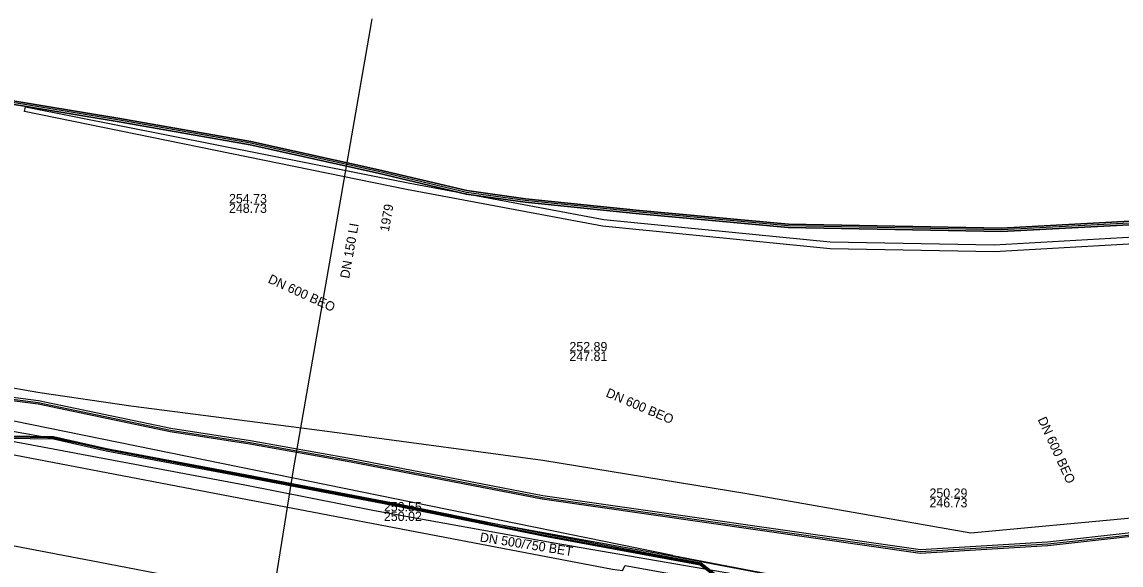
# Model space of a CAD drawing. Extents: x -599951 to -598963, y -1164095 to -1162939.
# Drawn here: x -599743.7 to -599648.8, y -1163069.7 to -1163022.9 of the extents above; entities that cross this region are included whole.
import ezdxf

# ---------------------------------------------------------------- set-up
doc = ezdxf.new("R2010")
doc.units = 0
for name, color, linetype in [('Level 3', 7, 'Continuous'), ('Vrstva 12', 7, 'Continuous'), ('Vrstva 13', 7, 'Continuous'), ('Vrstva 15', 7, 'Continuous'), ('Vrstva 20', 7, 'Continuous'), ('Vrstva 42', 7, 'Continuous'), ('Vrstva 44', 7, 'Continuous'), ('Vrstva 50', 7, 'Continuous'), ('Vrstva 55', 7, 'Continuous'), ('Vrstva 58', 7, 'Continuous')]:
    doc.layers.add(name, color=color, linetype=linetype)

msp = doc.modelspace()

# ---------------------------------------------------------------- linework, layer by layer
at = {"layer": 'Level 3'}
msp.add_lwpolyline([(-599673.93, -1163041.83), (-599659.8, -1163042.11), (-599643.7, -1163041.17), (-599629.45, -1163039.68), (-599616.06, -1163036.87), (-599614.07, -1163036.32), (-599613.87, -1163036.89), (-599615.9, -1163037.45), (-599629.35, -1163040.27), (-599643.66, -1163041.77), (-599659.78, -1163042.71), (-599673.95, -1163042.43), (-599693.58, -1163040.5), (-599710.47, -1163037.32), (-599743.44, -1163030.59), (-599743.36, -1163030.18), (-599710.35, -1163036.74), (-599693.46, -1163039.92)], close=True, dxfattribs=at)
at = {"layer": 'Vrstva 12'}
msp.add_line((-599687.5, -1163068.9), (-599771.04, -1163051.87), dxfattribs=at)
msp.add_lwpolyline([(-599687.5, -1163068.9), (-599664.38, -1163073.35), (-599656.95, -1163072.63), (-599653.54, -1163073.9), (-599642.67, -1163071.94), (-599630.66, -1163068.12), (-599627.43, -1163066.85)], dxfattribs=at)
at = {"layer": 'Vrstva 13'}
msp.add_lwpolyline([(-599713.474, -1163022.583), (-599713.543, -1163022.941), (-599715.989, -1163037.162), (-599720.271, -1163061.507), (-599722.794, -1163077.28), (-599723.393, -1163080.467), (-599723.56, -1163081.1)], dxfattribs=at)
at = {"layer": 'Vrstva 20'}
for points in [[(-599749, -1163058.61), (-599740.93, -1163058.73)], [(-599740.93, -1163058.73), (-599736.37, -1163059.77), (-599725.02, -1163061.91), (-599711.66, -1163064.47), (-599698.39, -1163067.17), (-599685.12, -1163069.63), (-599681.39, -1163072.5), (-599673.97, -1163073.86), (-599663.79, -1163075.59), (-599663.05, -1163075.2), (-599661.91, -1163074.71), (-599660.66, -1163074.4), (-599659.28, -1163074.73), (-599658.24, -1163075.53), (-599628.33, -1163084.93)]]:
    msp.add_lwpolyline(points, dxfattribs=at)
at = {"layer": 'Vrstva 42'}
for p, q in [((-599754.889, -1163052.719), (-599742.1, -1163054.827)), ((-599754.889, -1163052.719), (-599742.1, -1163054.827)), ((-599742.1, -1163054.827), (-599734.251, -1163055.996)), ((-599742.1, -1163054.827), (-599734.251, -1163055.996)), ((-599734.251, -1163055.996), (-599717.756, -1163058.123)), ((-599734.251, -1163055.996), (-599717.756, -1163058.123)), ((-599717.756, -1163058.123), (-599698.73, -1163060.68)), ((-599717.756, -1163058.123), (-599698.73, -1163060.68)), ((-599698.73, -1163060.68), (-599681.114, -1163063.552)), ((-599698.73, -1163060.68), (-599681.114, -1163063.552)), ((-599681.114, -1163063.552), (-599661.795, -1163066.958)), ((-599681.114, -1163063.552), (-599661.795, -1163066.958)), ((-599661.795, -1163066.958), (-599646.565, -1163065.518)), ((-599661.795, -1163066.958), (-599646.565, -1163065.518))]:
    msp.add_line(p, q, dxfattribs=at)
for points in [[(-599749.027, -1163029.218), (-599735.259, -1163031.487), (-599723.979, -1163033.467), (-599712.924, -1163035.926), (-599705.328, -1163037.718), (-599700.258, -1163038.429), (-599690.404, -1163039.429), (-599677.558, -1163040.61), (-599659.147, -1163040.95), (-599646.467, -1163040.28), (-599632.098, -1163038.578), (-599618.469, -1163036.179), (-599614.518, -1163035.737), (-599581.333, -1163024.559), (-599577.857, -1163022.879), (-599573.291, -1163020.673), (-599573.217, -1163020.469), (-599571.42, -1163019.6), (-599549.04, -1163007.06), (-599531.92, -1162994.62), (-599510.34, -1162973.32), (-599486.45, -1162944.12), (-599483.06, -1162939.4)], [(-599749.027, -1163029.218), (-599735.259, -1163031.487), (-599723.979, -1163033.467), (-599712.924, -1163035.926), (-599705.328, -1163037.718), (-599700.258, -1163038.429), (-599690.404, -1163039.429), (-599677.558, -1163040.61), (-599659.147, -1163040.95), (-599646.467, -1163040.28), (-599632.098, -1163038.578), (-599618.469, -1163036.179), (-599614.518, -1163035.737), (-599581.333, -1163024.559), (-599577.857, -1163022.879), (-599573.291, -1163020.673), (-599573.217, -1163020.469), (-599571.42, -1163019.6), (-599549.04, -1163007.06), (-599531.92, -1162994.62), (-599510.34, -1162973.32), (-599486.45, -1162944.12), (-599483.06, -1162939.4)], [(-599624.638, -1163023.389), (-599624.359, -1163023.956), (-599614.666, -1163035.452), (-599618.511, -1163035.881), (-599632.142, -1163038.282), (-599646.493, -1163039.98), (-599659.153, -1163040.65), (-599677.542, -1163040.31), (-599690.376, -1163039.131), (-599700.222, -1163038.131), (-599705.272, -1163037.422), (-599712.856, -1163035.634), (-599723.921, -1163033.173), (-599735.209, -1163031.191), (-599748.973, -1163028.922)], [(-599624.638, -1163023.389), (-599624.359, -1163023.956), (-599614.666, -1163035.452), (-599618.511, -1163035.881), (-599632.142, -1163038.282), (-599646.493, -1163039.98), (-599659.153, -1163040.65), (-599677.542, -1163040.31), (-599690.376, -1163039.131), (-599700.222, -1163038.131), (-599705.272, -1163037.422), (-599712.856, -1163035.634), (-599723.921, -1163033.173), (-599735.209, -1163031.191), (-599748.973, -1163028.922)], [(-599748.973, -1163028.922), (-599735.209, -1163031.191), (-599723.921, -1163033.173), (-599712.856, -1163035.634), (-599705.272, -1163037.422), (-599700.222, -1163038.131), (-599690.376, -1163039.131), (-599677.542, -1163040.31), (-599659.153, -1163040.65), (-599646.493, -1163039.98), (-599632.142, -1163038.282), (-599618.511, -1163035.881), (-599614.582, -1163035.443), (-599581.447, -1163024.281)], [(-599581.447, -1163024.281), (-599614.582, -1163035.443), (-599618.511, -1163035.881), (-599632.142, -1163038.282), (-599646.493, -1163039.98), (-599659.153, -1163040.65), (-599677.542, -1163040.31), (-599690.376, -1163039.131), (-599700.222, -1163038.131), (-599705.272, -1163037.422), (-599712.856, -1163035.634), (-599723.921, -1163033.173), (-599735.209, -1163031.191), (-599748.973, -1163028.922)], [(-599614.55, -1163035.59), (-599618.49, -1163036.03), (-599632.12, -1163038.43), (-599646.48, -1163040.13), (-599659.15, -1163040.8), (-599677.55, -1163040.46), (-599690.39, -1163039.28), (-599700.24, -1163038.28), (-599705.3, -1163037.57), (-599712.89, -1163035.78), (-599723.95, -1163033.32), (-599735.234, -1163031.339), (-599749, -1163029.07), (-599754.61, -1163027.92), (-599763.634, -1163026.393)], [(-599614.61, -1163035.986), (-599614.67, -1163035.754), (-599618.469, -1163036.179), (-599632.098, -1163038.578), (-599646.467, -1163040.28), (-599659.147, -1163040.95), (-599677.558, -1163040.61), (-599690.404, -1163039.429), (-599700.258, -1163038.429), (-599705.328, -1163037.718), (-599712.924, -1163035.926), (-599723.979, -1163033.467), (-599735.259, -1163031.487), (-599749.027, -1163029.218)], [(-599614.61, -1163035.986), (-599614.67, -1163035.754), (-599618.469, -1163036.179), (-599632.098, -1163038.578), (-599646.467, -1163040.28), (-599659.147, -1163040.95), (-599677.558, -1163040.61), (-599690.404, -1163039.429), (-599700.258, -1163038.429), (-599705.328, -1163037.718), (-599712.924, -1163035.926), (-599723.979, -1163033.467), (-599735.259, -1163031.487), (-599749.027, -1163029.218)], [(-599594.107, -1163066.854), (-599596.186, -1163064.179), (-599600.347, -1163061.392), (-599606.488, -1163055.75), (-599606.731, -1163055.367), (-599609.807, -1163050.419), (-599613.184, -1163042.889), (-599613.671, -1163039.223), (-599613.958, -1163036.325), (-599614.173, -1163035.305), (-599614.582, -1163035.443), (-599618.511, -1163035.881), (-599632.142, -1163038.282), (-599646.493, -1163039.98), (-599659.153, -1163040.65), (-599677.542, -1163040.31), (-599690.376, -1163039.131), (-599700.222, -1163038.131), (-599705.272, -1163037.422), (-599712.856, -1163035.634), (-599723.921, -1163033.173), (-599735.209, -1163031.191), (-599748.973, -1163028.922)], [(-599594.107, -1163066.854), (-599596.186, -1163064.179), (-599600.347, -1163061.392), (-599606.488, -1163055.75), (-599606.731, -1163055.367), (-599609.807, -1163050.419), (-599613.184, -1163042.889), (-599613.671, -1163039.223), (-599613.958, -1163036.325), (-599614.173, -1163035.305), (-599614.582, -1163035.443), (-599618.511, -1163035.881), (-599632.142, -1163038.282), (-599646.493, -1163039.98), (-599659.153, -1163040.65), (-599677.542, -1163040.31), (-599690.376, -1163039.131), (-599700.222, -1163038.131), (-599705.272, -1163037.422), (-599712.856, -1163035.634), (-599723.921, -1163033.173), (-599735.209, -1163031.191), (-599748.973, -1163028.922)], [(-599748.973, -1163028.922), (-599735.209, -1163031.191), (-599723.921, -1163033.173), (-599712.856, -1163035.634), (-599705.272, -1163037.422), (-599700.222, -1163038.131), (-599690.376, -1163039.131), (-599677.542, -1163040.31), (-599659.153, -1163040.65), (-599646.493, -1163039.98), (-599632.142, -1163038.282), (-599618.511, -1163035.881), (-599614.582, -1163035.443), (-599614.173, -1163035.305), (-599613.958, -1163036.325), (-599613.671, -1163039.223), (-599613.184, -1163042.889), (-599609.807, -1163050.419), (-599606.731, -1163055.367), (-599606.488, -1163055.75), (-599600.347, -1163061.392), (-599596.186, -1163064.179), (-599594.107, -1163066.854)], [(-599748.973, -1163028.922), (-599735.209, -1163031.191), (-599723.921, -1163033.173), (-599712.856, -1163035.634), (-599705.272, -1163037.422), (-599700.222, -1163038.131), (-599690.376, -1163039.131), (-599677.542, -1163040.31), (-599659.153, -1163040.65), (-599646.493, -1163039.98), (-599632.142, -1163038.282), (-599618.511, -1163035.881), (-599614.582, -1163035.443), (-599614.173, -1163035.305), (-599613.958, -1163036.325), (-599613.671, -1163039.223), (-599613.184, -1163042.889), (-599609.807, -1163050.419), (-599606.731, -1163055.367), (-599606.488, -1163055.75), (-599600.347, -1163061.392), (-599596.186, -1163064.179), (-599594.107, -1163066.854)], [(-599586.823, -1163034.366), (-599595.814, -1163040.283), (-599609.851, -1163050.611), (-599609.853, -1163050.613), (-599616.553, -1163055.342), (-599622.849, -1163059.853), (-599633.123, -1163063.742), (-599641.206, -1163066.066), (-599647.939, -1163067.259), (-599655.157, -1163068.06), (-599666.166, -1163068.721), (-599698.765, -1163064.048), (-599715.277, -1163060.847), (-599723.994, -1163059.298), (-599730.857, -1163058.248), (-599742.265, -1163055.848), (-599755.491, -1163054.139)], [(-599586.823, -1163034.366), (-599595.814, -1163040.283), (-599609.851, -1163050.611), (-599609.853, -1163050.613), (-599616.553, -1163055.342), (-599622.849, -1163059.853), (-599633.123, -1163063.742), (-599641.206, -1163066.066), (-599647.939, -1163067.259), (-599655.157, -1163068.06), (-599666.166, -1163068.721), (-599698.765, -1163064.048), (-599715.277, -1163060.847), (-599723.994, -1163059.298), (-599730.857, -1163058.248), (-599742.265, -1163055.848), (-599755.491, -1163054.139)], [(-599587.017, -1163034.134), (-599595.986, -1163040.037), (-599610.029, -1163050.369), (-599610.027, -1163050.367), (-599616.727, -1163055.098), (-599622.991, -1163059.587), (-599633.217, -1163063.458), (-599641.274, -1163065.774), (-599647.981, -1163066.961), (-599655.183, -1163067.76), (-599666.154, -1163068.419), (-599698.715, -1163063.752), (-599715.223, -1163060.553), (-599723.946, -1163059.002), (-599730.803, -1163057.952), (-599742.215, -1163055.552), (-599755.449, -1163053.841)], [(-599587.017, -1163034.134), (-599595.986, -1163040.037), (-599610.029, -1163050.369), (-599610.027, -1163050.367), (-599616.727, -1163055.098), (-599622.991, -1163059.587), (-599633.217, -1163063.458), (-599641.274, -1163065.774), (-599647.981, -1163066.961), (-599655.183, -1163067.76), (-599666.154, -1163068.419), (-599698.715, -1163063.752), (-599715.223, -1163060.553), (-599723.946, -1163059.002), (-599730.803, -1163057.952), (-599742.215, -1163055.552), (-599755.449, -1163053.841)], [(-599847.96, -1163035.87), (-599840.72, -1163037.45), (-599820.43, -1163040.74), (-599808.59, -1163042.52), (-599795.05, -1163045.1), (-599782.17, -1163047.94), (-599771.41, -1163051.51), (-599755.47, -1163053.99), (-599742.24, -1163055.7), (-599730.83, -1163058.1), (-599723.97, -1163059.15), (-599715.25, -1163060.7), (-599698.74, -1163063.9), (-599666.16, -1163068.57), (-599655.17, -1163067.91), (-599647.96, -1163067.11), (-599641.24, -1163065.92), (-599633.17, -1163063.6), (-599622.92, -1163059.72), (-599616.64, -1163055.22), (-599609.94, -1163050.49)], [(-599628.37, -1163086.37), (-599630.61, -1163086.08), (-599634.63, -1163085.25), (-599636.56, -1163084.87), (-599640.58, -1163084.16), (-599643.84, -1163083.58), (-599649.85, -1163082.43), (-599651.16, -1163082.29), (-599653.26, -1163082.4), (-599655.29, -1163082.76), (-599656.81, -1163083.2), (-599658.59, -1163083.79), (-599659.9, -1163084.03), (-599660.91, -1163084.02), (-599664.47, -1163083.38), (-599665.15, -1163083.2), (-599673.67, -1163081.73), (-599681.77, -1163080.21), (-599692, -1163078.2), (-599702.95, -1163076.09), (-599714.36, -1163073.83), (-599725, -1163071.8), (-599736.94, -1163069.5), (-599747.67, -1163067.47)]]:
    msp.add_lwpolyline(points, dxfattribs=at)
at = {"layer": 'Vrstva 44'}
msp.add_lwpolyline([(-599748.035, -1163058.372), (-599724.432, -1163062.801), (-599713.25, -1163065.019), (-599697.914, -1163067.775), (-599682.25, -1163070.502), (-599666.755, -1163073.705), (-599660.586, -1163074.868), (-599629.566, -1163083.973), (-599624.124, -1163084.818), (-599618.967, -1163086.117), (-599610.817, -1163087.733), (-599599.443, -1163089.526), (-599589.445, -1163091.26)], dxfattribs=at)
at = {"layer": 'Vrstva 50'}
msp.add_lwpolyline([(-599628.33, -1163084.93), (-599658.24, -1163075.53), (-599659.28, -1163074.73), (-599660.66, -1163074.4), (-599661.91, -1163074.71), (-599663.05, -1163075.2), (-599663.79, -1163075.59), (-599673.97, -1163073.86), (-599681.39, -1163072.5), (-599685.12, -1163069.63), (-599711.66, -1163064.47), (-599725.02, -1163061.91), (-599736.37, -1163059.77), (-599740.93, -1163058.73), (-599749, -1163058.61)], dxfattribs=at)
at = {"layer": 'Vrstva 55'}
for points in [[(-599753.62, -1163058.34), (-599753.67, -1163058.437), (-599721.636, -1163064.562)], [(-599721.636, -1163064.562), (-599692.72, -1163070.09), (-599691.84, -1163070.2), (-599691.62, -1163069.76), (-599670.25, -1163073.62), (-599663.86, -1163073.07), (-599663.93, -1163073.315)]]:
    msp.add_lwpolyline(points, dxfattribs=at)
at = {"layer": 'Vrstva 58'}
for points in [[(-599752.946, -1163056.655), (-599739.506, -1163059.075), (-599723.286, -1163062.295), (-599708.496, -1163065.135), (-599689.456, -1163068.595), (-599664.066, -1163073.415), (-599653.826, -1163076.325), (-599629.566, -1163083.125), (-599618.646, -1163085.265), (-599601.496, -1163088.275), (-599589.936, -1163090.325), (-599585.106, -1163090.775), (-599584.226, -1163091.175), (-599583.576, -1163092.035), (-599585.966, -1163102.435), (-599586.306, -1163105.375), (-599586.196, -1163105.675), (-599585.406, -1163105.925), (-599563.046, -1163110.065), (-599544.516, -1163113.655), (-599517.146, -1163118.855), (-599483.776, -1163125.315), (-599467.296, -1163128.595), (-599449.626, -1163131.895)], [(-599752.946, -1163056.655), (-599739.506, -1163059.075), (-599723.286, -1163062.295), (-599708.496, -1163065.135), (-599689.456, -1163068.595), (-599664.066, -1163073.415), (-599653.826, -1163076.325), (-599629.566, -1163083.125), (-599618.646, -1163085.265), (-599601.496, -1163088.275), (-599589.936, -1163090.325), (-599585.106, -1163090.775), (-599584.226, -1163091.175), (-599583.576, -1163092.035), (-599585.966, -1163102.435), (-599586.306, -1163105.375), (-599586.196, -1163105.675), (-599585.406, -1163105.925), (-599563.046, -1163110.065), (-599544.516, -1163113.655), (-599517.146, -1163118.855), (-599483.776, -1163125.315), (-599467.296, -1163128.595), (-599449.626, -1163131.895)], [(-599594.383, -1163068.513), (-599597.24, -1163069.57), (-599599.57, -1163071.13), (-599603.92, -1163073.29), (-599612.56, -1163076.48), (-599624.49, -1163081.4), (-599626.27, -1163082.43), (-599627.09, -1163083.57), (-599627.23, -1163084.67), (-599627.64, -1163085), (-599628.33, -1163084.93), (-599658.24, -1163075.53), (-599659.28, -1163074.73), (-599660.66, -1163074.4), (-599661.91, -1163074.71), (-599663.05, -1163075.2), (-599663.79, -1163075.59), (-599681.39, -1163072.5), (-599685.12, -1163069.63), (-599711.66, -1163064.47), (-599725.02, -1163061.91), (-599736.37, -1163059.77), (-599740.93, -1163058.73), (-599749, -1163058.61)], [(-599748.99, -1163058.51), (-599740.918, -1163058.63), (-599736.35, -1163059.672), (-599725.001, -1163061.812), (-599711.641, -1163064.372), (-599698.371, -1163067.072), (-599685.078, -1163069.536), (-599681.348, -1163072.406), (-599673.953, -1163073.762), (-599663.807, -1163075.486), (-599663.093, -1163075.11), (-599661.942, -1163074.615), (-599660.66, -1163074.297), (-599659.236, -1163074.638), (-599658.193, -1163075.44), (-599628.31, -1163084.832)], [(-599749.01, -1163058.71), (-599740.942, -1163058.83), (-599736.39, -1163059.868), (-599725.039, -1163062.008), (-599711.679, -1163064.568), (-599698.409, -1163067.268), (-599685.162, -1163069.724), (-599681.432, -1163072.594), (-599673.987, -1163073.958), (-599663.773, -1163075.694), (-599663.007, -1163075.29), (-599661.878, -1163074.805), (-599660.66, -1163074.503), (-599659.324, -1163074.822), (-599658.287, -1163075.62), (-599628.35, -1163085.028)], [(-599749.01, -1163058.71), (-599740.942, -1163058.83), (-599736.39, -1163059.868), (-599725.039, -1163062.008), (-599711.679, -1163064.568), (-599698.409, -1163067.268), (-599685.162, -1163069.724), (-599681.432, -1163072.594), (-599673.987, -1163073.958), (-599663.773, -1163075.694), (-599663.007, -1163075.29), (-599661.878, -1163074.805), (-599660.66, -1163074.503), (-599659.324, -1163074.822), (-599658.287, -1163075.62), (-599628.35, -1163085.028)]]:
    msp.add_lwpolyline(points, dxfattribs=at)

# ---------------------------------------------------------------- texts
at = {"layer": 'Vrstva 12'}
for s, p in [('254.73', (-599725.793, -1163038.507)), ('248.73', (-599725.793, -1163039.339)), ('252.89', (-599696.428, -1163051.281)), ('247.81', (-599696.428, -1163052.113)), ('250.29', (-599665.37, -1163063.923)), ('253.55', (-599712.432, -1163065.098)), ('246.73', (-599665.37, -1163064.755)), ('250.02', (-599712.432, -1163065.93))]:
    msp.add_text(s, height=0.8, dxfattribs=at).set_placement(p)
for s, rotation, p in [('DN 600 BEO', 335.46679, (-599722.491, -1163045.333)), ('DN 600 BEO', 337.00241, (-599693.347, -1163055.164)), ('DN 600 BEO', 294.58682, (-599656.055, -1163057.162)), ('DN 500/750 BET', 351.00792, (-599704.19, -1163067.697))]:
    msp.add_text(s, height=0.8, rotation=rotation, dxfattribs=at).set_placement(p)
at = {"layer": 'Vrstva 15'}
for s, rotation, p in [('1979', 80.21806, (-599712.004, -1163041.005)), ('DN 150 LI', 80.03674, (-599715.432, -1163045.044))]:
    msp.add_text(s, height=0.8, rotation=rotation, dxfattribs=at).set_placement(p)

doc.saveas('drawing.dxf')
